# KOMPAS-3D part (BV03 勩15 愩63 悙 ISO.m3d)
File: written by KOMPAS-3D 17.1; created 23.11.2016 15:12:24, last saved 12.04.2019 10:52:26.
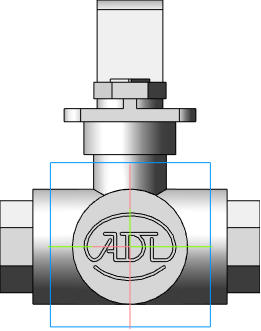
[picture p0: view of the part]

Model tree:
1. Операция без истории:2  (labels: Сталь 20  ГОСТ 1050-88)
